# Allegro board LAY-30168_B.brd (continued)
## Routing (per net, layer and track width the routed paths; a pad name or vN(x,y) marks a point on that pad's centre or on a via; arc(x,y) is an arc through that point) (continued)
VAUD_3V3: length 28.1
  TOP w0.254: v2(131.06,26.8) 130.92,26.66 U13.32 ; U13.8 125.88,27.79 125.48,28.19 v2(125.22,28.19)
  TOP w0.305: U13.10 124.71,26.16 124.62,26.07 123.92,26.07 123.57,26.42 v2(123.57,26.67) 123.57,27.3 C105.1 C104.1 123.06,29.22 R93.2
  TOP w0.381: R94.1 v2(139.31,25.17)
  BOTTOM w0.305: C106.1 128.65,27.3 128.91,27.56 129.54,27.56 C107.1 v2(131.06,26.8) 131.83,27.56 135.13,27.56 136.91,25.78 138.7,25.78 v2(139.31,25.17) ; C106.1 123.88,27.3 123.57,27 v2(123.57,26.67) ; C106.1 v2(125.22,28.19)
VLDO_3V3: length 40.5
  TOP w0.381: R42.1 35.43,42.42 v2(35.43,41.91)
  BOTTOM w0.381: v2(35.43,41.91) 36.07,42.55 37.34,42.55 44.58,35.31 46.23,35.31 47.5,34.04 49.91,34.04 51.56,32.38 51.56,26.92 54.86,23.62 54.86,16.51 v2(56.13,15.24)
VSD_3V3: length 49.1
  TOP w0.254: C30.1 27.81,38.09 U37.A2
  TOP w0.381: v2(19.94,54.86) 19.15,54.08 J39.4 10.8,54.08 10.41,53.7 v2(10.41,53.21) v2(10.41,52.07) 10.41,43.58 C242.1 10.43,41.77 17.65,34.54 26.93,34.54 27.81,35.43 27.81,36.44 C30.1
  BOTTOM w0.381: C160.1 v2(10.41,53.21) ; v2(10.41,52.07) C161.1 ; v2(19.94,54.86) 20.57,55.49 R371.1
VTRG_FAULT_B: length 25.2
  TOP w0.254: 129.29,66.17 U31.A2
  TOP w0.305: 129.29,66.17 R215.2 128.52,66.57 128.21,66.88 127.3,66.88 126.87,67.31 v2(126.87,68.07) ; U38.A8 125.89,76.17 124.84,77.22 122.56,77.22 v2(122.3,77.47)
  BOTTOM w0.305: v2(122.3,77.47) 121.54,76.71 121.54,69.09 122.56,68.07 v2(126.87,68.07)
WALL_OV_BASE: length 1.7
  TOP w0.381: Q3.1 15.09,19.82 14.61,20.31 R5.2
WALL_OV_CTL: length 2.3
  TOP w0.381: R3.2 14.1,18.92 R5.1 D1.C
WALL_OVP_LED: length 3.9
  TOP w0.381: R10.1 16.26,17.79 16.39,17.91 Q3.3 16.39,19.81 16.37,19.82 D2.A
WDOG_B: length 198.3
  TOP w0.127: v2(29.21,46.23) 28.07,47.37 28.07,56.9 27.43,57.53 27.43,63.17 31.98,67.72 52.67,67.72 54.1,69.15 68.47,69.15 77.56,78.25 99.93,78.25 104.19,73.99 104.19,58.59 102.68,57.09 86.72,57.09 85.26,58.55 65.76,58.55 64.73,57.52 U1.D14 ; C60.1 39.12,18.87 v2(38.86,18.62)
  BOTTOM w0.127: v2(38.86,18.62) 41.27,21.03 41.27,36.25 37.07,40.45 32.19,40.45 30.48,42.16 30.48,43.69 29.21,44.96 v2(29.21,46.23)
N99781517: length 16.7
  TOP w0.305: R15.1 78.74,35.57 80.44,33.87 D4.C 81.28,33.87 J5.1 ; v2(86.36,36.83) R16.2 87.26,37.84 86.78,38.31 D5.C
  BOTTOM w0.381: J5.1 v2(86.36,36.83)
N99781633: length 5.4
  TOP w0.203: C22.1 59.06,46.81 58.85,47.02 58.85,49.99 58.8,50.04 58.8,50.96 U1.P8
  TOP w0.305: C22.1 C21.1
N99781636: length 1.1
  TOP w0.254: U1.M10 v1(60.37,52)
  BOTTOM w0.254: v1(60.37,52) 60.2,51.82 C25.1
N99781637: length 11.1
  TOP w0.254: 65.48,48.06 63.71,48.06 63.46,48.31 62.39,48.31 60.33,50.38 60.33,50.74 U1.P10
  TOP w0.305: 65.48,48.06 66.68,46.86 C24.1 C26.1
N99781682: length 10.2
  TOP w0.127: Y2.1 64.4,45.21 64.27,45.34 C42.1 64.27,47.49 64.07,47.69 63.56,47.69 63.3,47.94 62.24,47.94 59.94,50.24 59.94,50.55 59.72,50.77 59.72,51.34 U1.N9
N99781687: length 8.9
  TOP w0.127: Y2.2 63.37,45.21 63.49,45.34 C43.1 63.49,47.23 63.1,47.62 62.12,47.62 59.65,50.1 59.65,50.46 59.4,50.71 U1.P9
N99781694: length 12.4
  TOP w0.127: U1.N11 61.03,51.34 61.03,50.71 61.57,50.16 62.39,50.16 63.14,49.42 64.88,49.42 65.02,49.28 66.29,49.28 67.44,48.13 C40.1 R28.2 68.71,47.36 68.83,47.49 68.83,48.13 68.96,48.26 Y1.1
N99781701: length 16.9
  TOP w0.127: U1.P11 60.7,50.61 61.39,49.91 62.21,49.91 63.01,49.11 64.68,49.11 64.9,48.9 66.04,48.9 67.56,47.37 67.56,46.23 67.96,45.83 C39.1 R28.1 68.63,46.61 69.13,47.11 71.13,47.11 71.34,46.9 Y1.3 R30.1
N99781716: length 6.3
  TOP w0.381: R19.1 64.09,39.37 C29.1 R18.2 67,40.84 67.01,40.85 U2.3
N99781728: length 3
  TOP w0.254: R20.1 R19.2 U2.2
N99781740: length 2
  TOP w0.127: C60.2 R45.1 D9.C
N99781746: length 4.7
  TOP w0.254: U5.3 40.98,21.42 40.25,20.69 R41.1 40.63,19.56 D9.A D8.A
N99781747: length 1.9
  TOP w0.381: R36.1 38.1,13.97
N99781749: length 10.9
  TOP w0.254: U5.2 38.78,21.22 39.5,20.49 R41.2 39.12,19.56 C54.1 R38.1 35.18,19.56 34.67,19.05 v2(34.67,18.01)
  TOP w0.381: U3.8 v2(34.67,18.01)
  BOTTOM w0.381: v2(34.67,18.01) 33.94,17.27 R35.2
N99781753: length 2.4
  TOP w0.127: D8.C R43.2 C58.1
N99781762: length 0.9
  BOTTOM w0.381: v2(32,17.4) 32.13,17.27 R35.1
N99781782: length 3.5
  TOP w0.381: U3.7 36.79,17.36 37.09,17.66 R39.1 R36.2
N99808656: length 15
  TOP w0.254: U1.J6 v1(57.12,54.59)
  INT1 w0.102: 56.8,52.97 56.34,52.97 56.15,52.78 56.15,52.3 56.17,52.32 57.27,52.32 57.44,52.49 57.44,52.96 57.12,53.29 56.8,52.97
  INT1 w0.305: v2(51.05,48.84) 51.64,48.84 52.58,49.78 53.14,49.78 55.42,52.07 55.92,52.07 56.15,52.3
  INT1 w0.33: 57.12,53.29 v1(57.12,54.59)
  BOTTOM w0.127: C77.1 v1(57.12,54.59)
  BOTTOM w0.305: v2(51.05,48.84) 51.44,49.23 51.44,49.78 R61.2
N99815013: length 4.1
  TOP w0.254: U16.3 v2(107.95,42.07)
  BOTTOM w0.381: L13.2 C140.1 C141.1 108.2,41.82 v2(107.95,42.07)
N99815680: length 2.9
  TOP w0.254: U16.2 107.45,42.33 v2(107.19,42.07)
  BOTTOM w0.381: C143.1 v2(107.19,42.07) 106.81,42.45 C142.1
N99815919: length 4.6
  TOP w0.254: C149.1 109.73,30.12 J19.6
N99815924: length 4.6
  TOP w0.254: J19.5 C150.1
N99816488:
  vias: v2(99.69,9.05) v2(100.97,9.05) v2(117.47,9.05) v2(118.75,9.05)
N99820323: length 3.4
  TOP w0.127: U16.10 111.74,44.25 112.17,43.81 112.78,43.81 113.07,43.52 113.07,43.05 R133.1
N99827287: length 1.9
  TOP w0.127: U13.27 C113.1
N99827729: length 3.4
  TOP w0.127: U13.15 124.62,23.65 122.93,21.96 R96.2
N99827749: length 2.5
  TOP w0.127: R98.2 123.71,24.14 124.22,24.65 U13.13
N99827769: length 2.4
  TOP w0.127: R99.2 123.3,25.41 123.56,25.15 U13.12
N99827789: length 4.1
  TOP w0.127: R100.2 123.44,20.83 123.44,21.84 124.75,23.15 U13.16
N99827809: length 2.8
  TOP w0.127: R101.2 123.34,22.88 124.61,24.15 U13.14
N99827829: length 3
  TOP w0.127: R102.2 122.93,26.29 123.56,25.66 U13.11
N99827958: length 5
  TOP w0.381: R118.2 C134.2 145.55,20.72 C232.1 145.54,20.07 146.69,18.92 J16.1
N99827962: length 4.8
  TOP w0.381: R120.2 C136.1 144.04,20.7 C232.2 144.79,19.69 144.15,19.05 J16.2
N99828318: length 5
  TOP w0.381: J17.1 139.7,18.92 138.68,19.95 C233.1 139.44,20.7 C135.2 139.46,20.72 R119.2
N99828322: length 4.9
  TOP w0.381: R121.2 136.16,20.71 C137.1 137.92,20.71 C233.2 137.93,19.95 137.16,19.18 J17.2
N99833003:
  vias: v2(88.9,2.54) v2(94.03,2.54)
N99833020: length 10.5
  TOP w0.127: R71.1 v2(93.34,7.09) 93.34,6.23 92.09,4.97 J9.4 ; U9.3 90.18,9.49 v2(89.79,9.88)
  BOTTOM w0.127: v2(89.79,9.88) 90.55,9.12 91.69,9.12 92.08,8.74 92.08,7.75 92.74,7.09 v2(93.34,7.09)
N99833038: length 15.2
  TOP w0.119: R68.1 L5.1 v2(91.33,10.01) 91.18,9.86 U9.1 ; J9.2 90.79,4.82 91.02,5.05 91.02,5.38 91.76,6.11 91.76,6.28 91.64,6.4 v2(91.51,6.4)
  BOTTOM w0.119: v2(91.33,10.01) 91.15,10.18 91.15,10.79 90.58,11.35 89.49,11.35 89.03,10.9 89.03,7.88 89.78,7.13 91.4,7.13 91.68,6.84 91.68,6.57 v2(91.51,6.4)
N99833040: length 15.3
  TOP w0.119: R69.1 L5.4 v2(90.53,10.01) 90.68,9.86 U9.2 ; v2(92.35,6.4) 92.2,6.4 92,6.21 92,6.01 91.27,5.28 91.27,5.06 91.44,4.88 J9.3
  BOTTOM w0.119: v2(90.53,10.01) 90.7,10.01 90.91,10.22 90.91,10.68 90.48,11.11 89.59,11.11 89.27,10.79 89.27,7.98 89.88,7.37 90.5,7.37 90.62,7.49 90.62,7.6 90.74,7.71 90.98,7.71 91.1,7.6 91.1,7.49 91.22,7.37 91.5,7.37 91.92,6.95 91.92,6.61 92.13,6.4 v2(92.35,6.4)
N99834989:
  vias: v2(78.23,2.54) v2(83.36,2.54)
N99835007: length 12.2
  TOP w0.119: U11.1 80.51,9.86 v2(80.66,10.01) L8.1 R83.1 ; v2(81.37,8.16) 81.67,7.86 81.67,7.09 80.32,5.75 80.32,5.15 80.12,4.95 J10.2
  BOTTOM w0.119: v2(80.66,10.01) 80.43,10.01 80.31,10.13 80.31,10.45 80.43,10.57 81.26,10.57 81.82,10.01 81.82,9.36 81.7,9.24 81.6,9.24 81.48,9.12 81.48,8.89 81.6,8.77 81.7,8.77 81.82,8.65 81.82,8.42 81.56,8.16 v2(81.37,8.16)
N99835017: length 12.2
  TOP w0.119: J10.3 80.77,4.95 80.57,5.15 80.57,5.65 81.92,6.99 81.92,7.86 v2(82.21,8.16) ; R84.1 L8.4 v2(79.86,10.01) 80.01,9.86 U11.2
  BOTTOM w0.119: v2(82.21,8.16) 82.06,8.31 82.06,10.11 81.36,10.82 80.33,10.82 80.07,10.55 80.07,10.22 v2(79.86,10.01)
N99838171: length 1
  TOP w0.127: R175.1 D12.C
N99842431: length 4.6
  TOP w0.254: R115.2 123.45,55.83 123.63,56.01 124.61,56.01 124.84,56.24 124.84,56.6 124.66,56.78 U14.1
  TOP w0.381: R114.1 122.68,55.12 122.95,55.38 R115.2
N99842486: length 1.5
  TOP w0.381: C139.1 R122.2
N99842500: length 1.7
  TOP w0.508: T1.1 C131.2
N99842510: length 3.8
  TOP w0.508: R116.1 C132.1 T1.6
N99842524: length 1
  TOP w0.381: R115.1 C132.2
N99842534: length 10.4
  TOP w0.254: v2(124.97,58.04) 124.73,57.8 U14.3 ; v2(120.52,55.38) 120.79,55.12 R114.2 121.29,55.37 122.04,56.12 R117.1 122.5,56.34 122.95,56.78 U14.6
  BOTTOM w0.305: v2(124.97,58.04) 123.18,58.04 v2(120.52,55.38)
N99842546: length 5.5
  TOP w0.254: U14.4 122.92,57.8 122.56,58.17
  TOP w0.381: J15.2 120.02,60.71 122.56,58.17
N99842626: length 6.2
  TOP w0.127: J38.1 121.01,47.88 R124.1 121.68,49.42 122.3,50.04 122.3,51.32 122.17,51.44 U15.2
N99842704: length 12.4
  TOP w0.508: J18.1 143.67,47.89 143.16,48.4 T2.3
N99903207: length 1.9
  TOP w0.381: L10.1 R97.2 C230.2
N99903209: length 2.1
  TOP w0.381: L11.1 R103.1 133.73,25.78 C231.2
N99903219: length 30.9
  TOP w0.381: v2(136.14,23.75) C115.1 L11.2 ; TVS4.2 138.55,37.6 v2(138.68,37.47)
  TOP w0.508: J12.3 TVS4.2
  BOTTOM w0.381: v2(136.14,23.75) 137.41,23.75 138.18,24.51 140.59,24.51 141.99,25.91 143.89,25.91 144.4,26.42 144.4,27.56 144.02,27.94 139.95,27.94 137.9,30 137.9,36.68 v2(138.68,37.47)
N99903223: length 8.6
  TOP w0.381: L10.2 C114.2 136.02,28.96 136.4,28.57 136.4,26.42 136.82,26 TVS2.2
  TOP w0.508: TVS2.2 137.9,26.1 J12.2
N99903738: length 15.1
  TOP w0.381: L12.2 v2(132.59,33.27)
  BOTTOM w0.305: v2(132.59,33.27) 132.59,31.65 137.31,26.92 v2(143.51,26.92)
N99904959: length 2.4
  TOP w0.305: R110.1 R107.2 C123.2
N99904961: length 4.3
  TOP w0.305: L12.1 C129.1 C128.1 129.67,31.88 C125.2
N99904975: length 2.7
  TOP w0.305: R107.1 R104.2 C119.1 C120.1
N99907436: length 1.8
  TOP w0.305: R113.2 R112.2 123.87,33.54 C124.2
N99907447: length 6.8
  TOP w0.305: R111.2 123.69,34.79 123.56,34.66 R109.2 R112.1 v2(125.22,34.29)
  TOP w0.381: C126.1 v2(126.11,31.24)
  BOTTOM w0.305: v2(125.22,34.29) 125.22,32.13 v2(126.11,31.24)
N99907449: length 8.8
  TOP w0.305: R108.2 122.69,34.79 122.82,34.66 R109.1 R106.2 v2(121.16,34.29)
  TOP w0.381: C122.1 v2(124.33,31.24)
  BOTTOM w0.305: v2(121.16,34.29) 121.16,32.64 122.56,31.24 v2(124.33,31.24)
N99907458: length 3.6
  TOP w0.305: C124.1 122.51,33.54 R106.1 R105.2 C116.1 C117.1
N99907542: length 3.3
  TOP w0.305: P1.1 122.24,37.27 122.69,36.82 R108.1
N99907546: length 3.3
  TOP w0.305: R111.1 123.69,36.82 124.14,37.27 P1.2
N99909350: length 5.8
  TOP w0.254: R269.1 R268.2 U32.7
N99909356: length 2.8
  TOP w0.254: U32.16 R266.1
N99909379: length 4.9
  TOP w0.254: U32.6 60.46,73.29 59.69,72.52 R273.1
N99909383: length 3.9
  TOP w0.254: R272.1 U32.4
N99909400: length 3.8
  TOP w0.254: C190.1 57.02,78.23 57.28,77.97 U32.2
N99909418: length 5.3
  TOP w0.254: C189.1 61.46,73.79 U32.8
N99909466: length 4.9
  TOP w0.254: R264.1 66.04,75.56 65.13,76.47 U32.9
N99909468: length 5
  TOP w0.254: U32.11 65.28,77.47 66.42,78.61 R263.1
N99909488: length 5.8
  TOP w0.254: R265.2 R267.1 66.04,76.58 65.65,76.97 U32.10
N99912703: length 3.3
  TOP w0.305: U8.5 v2(94.36,66.68) C88.1 R63.1
  vias: v2(100.71,68.71) v2(101.35,68.71)
N99917011: length 12.6
  BOTTOM w0.254: J26.2 22.86,37.99 J25.3
N99917059: length 142.9
  TOP w0.127: J24.9 4.33,79.41 4.33,32.25 8.89,27.69 25.78,27.69 28.32,25.15 28.32,14.69 30.1,12.91 30.1,3.3 31.74,1.66 71.63,1.66 R276.1
N99917061: length 144.6
  TOP w0.127: J24.10 3.7,79.88 3.7,31.99 8.51,27.18 25.57,27.18 27.81,24.94 27.81,14.48 29.59,12.7 29.59,3.3 31.53,1.36 72.35,1.36 R277.1
N99917215: length 3.3
  TOP w0.381: D14.C J25.5
N100002783: length 3.4
  TOP w0.254: U1.K3 v1(55.17,53.3)
  BOTTOM w0.102: v1(55.17,53.3) 54.85,52.97 54.85,52.25 C41.1 54.18,52.02 53.87,51.71 R32.2
N100054133: length 4
  TOP w0.381: Q4.1 17.48,14.15 17.01,14.61 R11.1 R10.2
N100054253: length 14.5
  TOP w0.381: D2.C R4.2 16.37,23.86 16.5,24 C5.2 R8.1 v2(17.4,23.5) ; Q2.3 v2(9.88,18.41)
  BOTTOM w0.381: v2(17.4,23.5) 12.32,18.41 v2(9.88,18.41)
N100054255: length 1
  TOP w0.381: R8.2 R9.1
N100054257: length 20.9
  TOP w0.381: R9.2 v2(20.45,23.5)
  BOTTOM w0.381: v2(20.45,23.5) 18.54,21.59 18.54,10.65 SW1.5
N100054299: length 7
  TOP w0.254: R4.1 15.62,22.63 15.62,20.29 15.72,20.19 15.72,18.65 15.37,18.3 Q3.2 14.97,18.3
  TOP w0.381: R4.1 15.62,24.13 15.49,24.26 C5.1
N100054525: length 2
  TOP w0.381: D3.3 R7.2
N100054552: length 1.9
  TOP w0.381: D3.1 v2(17.4,20.02)
  BOTTOM w0.381: R6.2 v2(17.4,20.02)
N100054568: length 2.2
  TOP w0.381: Q4.3 D3.2
N100192090: length 4.5
  TOP w0.127: v2(135.76,6.1) 135.96,6.3 J35.19
  BOTTOM w0.127: R230.2 136.02,6.36 v2(135.76,6.1)
N100192374: length 4
  TOP w0.127: L17.1 139.57,10.04 139.57,9.86 137.96,8.25 J35.23
N100226351: length 1.9
  TOP w0.127: SW7.5 R246.2
N100226419: length 1.9
  TOP w0.127: SW7.6 R245.2
N100226426: length 1.9
  TOP w0.127: SW7.7 R244.2
N100226433: length 1.9
  TOP w0.127: SW7.8 R243.2
N100226440: length 1.9
  TOP w0.127: SW6.5 R242.2
N100226447: length 1.9
  TOP w0.127: SW6.6 R241.2
N100226454: length 1.9
  TOP w0.127: SW6.7 R240.2
N100226461: length 1.9
  TOP w0.127: SW6.8 R239.2
N100226670: length 1.9
  TOP w0.127: SW5.5 R238.2
N100226677: length 1.9
  TOP w0.127: SW5.6 R237.2
N100226684: length 1.9
  TOP w0.127: SW5.7 R236.2
N100226691: length 1.9
  TOP w0.127: SW5.8 R235.2
N100290781: length 3.7
  BOTTOM w0.127: R67.2 J8.A31
N100350746: length 3.1
  TOP w0.305: R27.2 D7.A D6.A R29.1
N100395820: length 4.5
  TOP w0.508: C131.1 135.89,57.4 136.4,57.91 139.16,57.91 J14.2
N100395835: length 11.6
  TOP w0.508: J14.1 143.67,59.66 142.86,60.46 T1.3
N100538650: length 6.5
  TOP w0.381: Q9.3 44.45,36.45 44.83,36.83 44.83,38.48 44.38,38.94 R47.2
N100585505: length 3.9
  TOP w0.127: J39.9 24.11,56.28 v2(24.13,56.26)
  BOTTOM w0.127: R313.2 R173.1 v2(24.13,56.26) R320.1
N100756566: length 19.3
  TOP w0.254: TP22.1 v2(73.79,44.96) ; U1.N10 v1(60.37,51.35)
  BOTTOM w0.254: v1(60.37,51.35) 60.92,51.35 62.76,49.5 72.29,49.5 73.23,48.56 73.23,45.52 v2(73.79,44.96)
N100757315: length 5.7
  TOP w0.102: U1.N12 61.68,51.34 61.68,50.9 61.89,50.69 62.62,50.69 62.99,50.32 63.47,50.32
  TOP w0.254: 63.47,50.32 64.03,50.32 64.34,50.62 TP23.1
N100763661: length 26.4
  TOP w0.127: J24.5 15.68,65.53 15.55,65.41 14.73,65.41 14.61,65.28 14.61,65.03 14.73,64.9 15.68,64.9 15.81,64.77 15.81,64.52 15.68,64.39 14.73,64.39 14.61,64.26 14.61,64.01 14.73,63.88 15.68,63.88 15.81,63.76 15.81,63.5 15.68,63.38 14.99,63.38 14.86,63.25 14.86,62.99 14.99,62.87 15.55,62.87 15.68,62.74 15.68,61.4 v2(15.24,60.96)
  BOTTOM w0.127: R278.1 15.11,60.83 v2(15.24,60.96)
N100763684: length 27.6
  TOP w0.127: v2(17.27,58.93) 17.27,61.47 18.03,62.23 18.03,62.7 17.91,62.82 17.35,62.82 17.22,62.95 17.22,63.2 17.35,63.33 18.09,63.33 18.22,63.46 18.22,63.71 18.09,63.84 17.4,63.84 17.27,63.97 17.27,64.22 17.4,64.35 18.09,64.35 18.22,64.47 18.22,64.73 18.09,64.85 17.4,64.85 17.27,64.98 17.27,65.24 17.4,65.36 18.09,65.36 18.22,65.49 J24.4
  BOTTOM w0.127: R279.1 17.27,58.92 v2(17.27,58.93)
N100763722: length 26.8
  TOP w0.127: J24.6 13.14,61.21 v2(13.39,60.96)
  BOTTOM w0.127: v2(13.39,60.96) 13.39,58.49 15.11,56.77 R280.1
N100763741: length 28.6
  TOP w0.127: v2(17.78,57.27) 17.91,57.4 17.91,60.07 20.19,62.36 20.19,63.48 20.07,63.6 19.79,63.6 19.66,63.73 19.66,63.98 19.79,64.11 20.63,64.11 20.76,64.24 20.76,64.49 20.63,64.62 19.79,64.62 19.66,64.75 19.66,65 19.79,65.13 20.63,65.13 20.76,65.25 J24.3
  BOTTOM w0.127: R281.1 v2(17.78,57.27)
N100763780: length 19.5
  TOP w0.127: U20.F2 32.47,60.57 32.47,62.06 33.02,62.61 33.38,62.61 33.51,62.48 33.51,61.98 33.64,61.85 33.89,61.85 34.02,61.98 34.02,62.48 34.15,62.61 34.4,62.61 34.53,62.48 34.53,61.98 34.65,61.85 34.91,61.85 35.04,61.98 35.04,62.48 35.16,62.61 35.42,62.61 35.54,62.48 35.54,61.98 35.67,61.85 35.92,61.85 36.05,61.98 36.05,62.48 36.18,62.61 36.43,62.61 36.56,62.48 36.56,61.98 36.69,61.85 36.94,61.85 37.07,61.98 37.07,62.48 37.19,62.61 37.45,62.61 37.58,62.48 37.58,61.98 37.7,61.85 37.96,61.85 38.08,61.98 38.08,62.48 38.21,62.61 38.46,62.61 38.59,62.48 38.59,62.1 38.72,61.98 38.97,61.98 39.1,62.1 39.1,62.48 39.23,62.61 39.56,62.61 39.69,62.48 39.69,62.1 39.81,61.98 40.07,61.98 40.19,62.1 40.19,62.74 40.32,62.87 40.77,62.87 40.9,62.74 R283.2
N100784802: length 62.9
  TOP w0.127: v2(66.55,30.73) 65.98,30.16 52.01,30.16 51.18,29.34 37.98,29.34 J23.1
  BOTTOM w0.127: v2(66.55,30.73) 73.41,30.73 79.76,37.08 79.76,48.13 80.78,49.16 R285.1
N100784828: length 59.4
  TOP w0.127: J23.2 40.01,29.84 50.8,29.84 51.69,30.73 v2(65.41,30.73)
  BOTTOM w0.127: R286.1 79.88,49.15 79.38,48.64 79.38,37.34 73.28,31.24 65.91,31.24 v2(65.41,30.73)
N100784849: length 115.6
  TOP w0.127: R287.1 91.31,52.96 92.08,52.96 92.76,52.27 102.92,52.27 108.09,57.45 108.09,78.35 103.76,82.68 95.63,82.68 92.08,86.23 56.39,86.23 49.4,79.25 41.41,79.25 J22.4
N100784872: length 111.3
  TOP w0.127: v2(86.56,50.8) 103.28,50.8 110.26,57.78 v2(112.39,57.78)
  BOTTOM w0.127: v2(86.56,50.8) 86.99,50.37 R288.1 ; v2(112.39,57.78) 112.39,61.59 87.07,86.92 62.79,86.92 56.47,80.6 J22.1
N100784902: length 112.2
  BOTTOM w0.127: J22.2 46.33,81.79 54.36,81.79 59.8,87.23 87.34,87.23 113.03,61.54 113.03,54.86 118.24,49.66 118.24,34.49 117.35,33.6 R289.1
N100784935: length 66.1
  TOP w0.127: v2(65.41,31.75) 51.69,31.75 50.29,30.35 42.05,30.35 J23.3 ; v2(87.63,48.01) 86.11,48.01 84.72,49.39 83.63,49.39 83.28,49.73 78.41,49.73 v2(78.23,49.91)
  BOTTOM w0.127: R290.1 v2(87.63,48.01) ; v2(65.41,31.75) 66.67,33.02 71.88,33.02 75.82,36.96 75.82,49.91 76.33,50.42 77.72,50.42 v2(78.23,49.91)
N100784954: length 64.9
  TOP w0.127: v2(88.77,45.85) 87,47.62 86.03,47.62 84.57,49.09 83.48,49.09 83.14,49.43 77.19,49.43 v2(76.71,49.91) ; J23.4 44.08,30.86 49.91,30.86 51.31,32.26 66.04,32.26 v2(66.55,31.75)
  BOTTOM w0.127: v2(66.55,31.75) 67.3,32.5 72.12,32.5 76.26,36.64 76.26,49.47 v2(76.71,49.91) ; R291.1 v2(88.77,45.85)
N100873109: length 1.1
  TOP w0.381: R18.1 68.07,38.62 R293.2
N100881534: length 20.4
  TOP w0.127: v2(56.13,27.56) 55.75,27.18 U33.6
  BOTTOM w0.127: v2(56.13,27.56) 56.13,28.87 56.01,28.99 55.63,28.99 55.5,29.12 55.5,29.38 55.63,29.5 56.01,29.5 56.13,29.63 56.13,29.88 56.01,30.01 55.5,30.01 55.37,30.14 55.37,30.39 55.5,30.52 56.01,30.52 56.13,30.65 56.13,30.9 56.01,31.03 55.5,31.03 55.37,31.15 55.37,31.41 55.5,31.53 56.01,31.53 56.13,31.66 56.13,32 52.32,35.81 52.32,39.52 52.63,39.83 52.63,40.65 R154.2
N100881537: length 21.3
  TOP w0.127: v2(59.18,24.89) 59.44,24.64 U33.1
  BOTTOM w0.127: R153.2 50.29,38.49 50.3,38.48 50.3,35.93 53.09,33.15 53.09,29.84 58.05,24.89 R360.2 58.3,24.89 v2(59.18,24.89)
N100881743: length 19.7
  TOP w0.127: U33.5 v2(57.91,28.45)
  BOTTOM w0.127: R155.1 55.18,35.88 55.18,35.7 54.72,35.24 54.72,35.06 54.9,34.88 55.08,34.88 55.54,35.34 55.72,35.34 55.87,35.2 55.87,35.02 55.4,34.55 55.4,34.37 55.58,34.19 55.76,34.19 56.16,34.59 56.34,34.59 56.55,34.38 56.55,34.2 56.09,33.75 56.09,33.57 56.27,33.39 56.45,33.39 56.78,33.72 56.96,33.72 57.15,33.53 57.78,33.53 57.91,33.4 57.91,33.06 57.78,32.94 57.4,32.94 57.28,32.81 57.28,32.56 57.4,32.43 57.78,32.43 57.91,32.3 57.91,32.05 57.78,31.92 57.4,31.92 57.28,31.79 57.28,31.46 57.4,31.33 57.78,31.33 57.91,31.2 57.91,30.95 57.78,30.82 57.4,30.82 57.28,30.7 57.28,29.08 v2(57.91,28.45)
N100881750: length 20.4
  TOP w0.127: v2(59.18,25.91) U33.2
  BOTTOM w0.127: v2(59.18,25.91) 58.93,25.91 58.4,26.43 58.22,26.43 57.83,26.04 57.65,26.04 57.47,26.22 57.47,26.4 58.24,27.17 58.24,27.35 58.07,27.53 57.89,27.53 57.11,26.76 56.93,26.76 56.75,26.94 56.75,27.12 57.15,27.51 57.15,27.69 56.64,28.19 56.64,32.35 53.59,35.4 53.59,35.72 53.72,35.85 53.98,35.85 54.1,35.98 54.1,36.23 53.98,36.36 53.72,36.36 53.59,36.49 R156.1
N100881757: length 20.4
  TOP w0.127: v2(60.07,27.18) U33.3
  BOTTOM w0.127: R157.1 58.16,38.49 59.69,36.96 59.69,36.4 59.82,36.27 60.07,36.27 60.2,36.15 60.2,35.89 60.07,35.76 59.44,35.76 59.31,35.64 59.31,35.4 59.44,35.27 60.07,35.27 60.2,35.15 60.2,34.89 60.07,34.77 59.82,34.77 59.69,34.64 59.69,34.39 59.82,34.26 60.07,34.26 60.2,34.13 60.2,33.88 60.07,33.75 59.82,33.75 59.69,33.62 59.69,33.37 59.82,33.24 60.07,33.24 60.2,33.12 60.2,32.86 60.07,32.73 59.82,32.73 59.69,32.61 59.69,32.35 59.82,32.23 60.07,32.23 60.2,32.1 60.2,31.85 60.07,31.72 59.69,31.72 59.56,31.59 59.56,31.27 59.69,31.14 60.05,31.14 60.17,31.01 60.17,30.76 60.05,30.63 59.82,30.63 59.69,30.51 59.69,29.84 60.71,28.83 R359.2 v2(60.07,27.18)
N100881764: length 20.8
  TOP w0.127: v2(59.18,28.45) 56.64,25.91 U33.7
  BOTTOM w0.127: R358.2 v2(59.18,28.45) 58.35,29.28 58.35,29.75 58.23,29.88 58.04,29.88 57.91,30 57.91,30.26 58.04,30.39 58.61,30.39 58.73,30.51 58.73,30.77 58.61,30.89 58.48,30.89 58.35,31.02 58.35,31.99 58.48,32.12 58.93,32.12 59.05,32.24 59.05,32.5 58.93,32.62 58.48,32.62 58.35,32.75 58.35,33 58.48,33.13 58.93,33.13 59.05,33.26 59.05,33.51 58.93,33.64 58.48,33.64 58.35,33.77 58.35,34.04 58.48,34.17 59.05,34.17 59.18,34.3 59.18,34.54 59.05,34.67 58.55,34.67 58.42,34.8 58.42,36.46 R158.1
N100937722: length 2.1
  TOP w0.127: U19.A4 55.74,42.31 v1(55.63,42.42)
  BOTTOM w0.127: R169.2 55.89,42.16 v1(55.63,42.42) 55.63,42.53 55.58,42.58 R168.2
N100939369: length 2.7
  BOTTOM w0.127: R425.1 R424.1 R171.2 R427.2
N100979684: length 2.5
  TOP w0.381: R305.2 57.16,10.41 R304.1 55.98,9.53 U4.4
N101050998: length 4.4
  TOP w0.127: U16.32 105.98,43.75 104.78,42.55 C234.1 103.64,42.55 R322.1 R323.2
N101100421: length 2
  BOTTOM w0.127: R313.1 R372.2 R371.2
N101108824: length 1.5
  TOP w0.127: D18.A 100.83,40.13 R316.2
N101140611: length 6.5
  TOP w0.127: Q15.3 81.92,15.62 82.29,15.25 R329.2 R333.1 R332.2 85.83,15.14 U34.A1
N101140956: length 3.6
  TOP w0.127: U34.A2 86.23,14.74 R349.2 R334.2
N101141371: length 3.1
  TOP w0.127: R335.1 86.63,12.97 U34.A3
N101141921: length 4
  TOP w0.102: U35.A2 89.03,23.62
  TOP w0.127: R341.2 R350.2 89.03,25.15 89.03,23.62
N101141946: length 3.5
  TOP w0.102: U35.A3 89.43,23.39 89.66,23.62
  TOP w0.127: 89.66,23.62 R342.1
N101142201: length 5
  TOP w0.102: U35.A1 88.63,23.62
  TOP w0.127: R344.2 R346.2 R348.1 88.63,25.3 88.63,23.62
N101241745: length 4.7
  TOP w0.381: U12.3 v2(74.05,21.21)
  BOTTOM w0.381: v2(74.05,21.21) 73.91,21.35 C99.1 C98.1 74.8,20.58 R85.2
N101242370: length 7.6
  TOP w0.127: R88.2 v2(63.92,12.11) ; R89.1 v2(68.94,12.11)
  BOTTOM w0.127: v2(63.92,12.11) 64.18,11.85 C102.1 68.69,11.85 v2(68.94,12.11)
N101242461: length 14.8
  TOP w0.107: R87.1 FL1.4 66.2,17.26 66.3,17.37 66.3,18.28 67.07,19.05 74.43,19.05 74.82,18.66 74.82,18.4 74.92,18.29 75.22,18.29 75.32,18.19 U12.7
N101242463: length 14.4
  TOP w0.107: U12.6 74.05,18.19 74.16,18.29 74.45,18.29 74.56,18.4 74.56,18.55 74.32,18.79 73.83,18.79 73.73,18.68 73.73,18.52 73.62,18.41 73.41,18.41 73.3,18.52 73.3,18.68 73.19,18.79 67.18,18.79 66.56,18.18 66.56,17.37 66.67,17.26 FL1.3 R91.1
N101242940: length 3.8
  TOP w0.127: U12.8 v2(76.59,16) 76.59,15.25 R326.1
  BOTTOM w0.127: R90.2 R92.2 v2(76.59,16)
N101351285: length 4
  TOP w0.127: U19.C2 53.24,40.26 52.7,40.26 52.07,40.89 v1(51.92,40.89)
  BOTTOM w0.127: v1(51.92,40.89) R356.2 51.05,40.26 R294.2
N101351783: length 3.7
  TOP w0.127: J35.21 136.96,6.55 v2(137.54,5.97)
  BOTTOM w0.127: v2(137.54,5.97) 137.67,6.1 C248.1 137.67,7.74 L19.1
N101474013: length 1.2
  TOP w0.127: U19.B2 53.39,40.76 v1(53.21,40.94)
  BOTTOM w0.127: R361.2 53.28,41.01 v1(53.21,40.94)
N101474117: length 1.3
  TOP w0.127: U19.D3 54.74,38.48 v1(54.99,38.23)
  BOTTOM w0.127: v1(54.99,38.23) R362.2
N101474142: length 1.2
  TOP w0.102: U19.D2 53.95,38.76 v1(54.23,38.48)
  BOTTOM w0.102: R363.2 53.6,38.48 v1(54.23,38.48)
N101474197: length 1.7
  TOP w0.127: v1(56.39,40.26) 55.89,39.76 U19.C4
  BOTTOM w0.127: R364.2 56.65,40 v1(56.39,40.26)
N101474201: length 1.5
  TOP w0.127: U19.D4 56.02,38.48 v1(56.26,38.48)
  BOTTOM w0.127: v1(56.26,38.48) 56.39,38.48 R365.2
N101481296: length 1.5
  TOP w0.127: U19.C3 54.6,39.76 v1(54.1,40.26)
  BOTTOM w0.127: R366.2 54.23,40.39 v1(54.1,40.26)
N101508071: length 3.1
  TOP w0.254: U37.B1 28.52,40.01 28.45,40.07 R29.2
N101529304: length 3.4
  TOP w0.305: U38.E4 v2(130.01,72.57) ; U38.E5 v2(130.01,73.37) ; U38.F4 v2(130.81,72.57)
  BOTTOM w0.305: C254.1 130.18,73.53 v2(130.01,73.37) ; 130.94,71.75 130.81,71.88 v2(130.81,72.57)
  vias: v2(125.48,65.41) v2(126.36,66.05) v2(126.36,65.41)
N101531474: length 2.7
  TOP w0.127: U40.4 145.09,83.38 144.91,83.56 R377.1 R378.2
N101535047: length 9.1
  TOP w0.127: U38.E3 130.81,71.77 130.81,70.23 131.83,69.22 136.65,69.22 R379.2
N101535139: length 7.9
  TOP w0.127: R380.2 136.65,70.87 135.76,69.98 132.84,69.98 132.42,70.4 132.42,71.53 132.17,71.77 131.6,71.77 U38.F3
N101537312: length 3.5
  TOP w0.127: U38.A6 124.44,74.57 R381.2
N101537315: length 4.7
  TOP w0.127: R382.2 125.06,74.96 127.37,74.96 127.77,74.57 U38.B6
N101537383: length 3.8
  TOP w0.127: U38.A4 125.42,72.97 124.46,72.01 R383.2
N101544777: length 5.5
  TOP w0.127: R387.2 125.6,78.49 126.73,77.36 128.25,77.36 128.64,76.97 U38.C9
N101546218: length 1.5
  TOP w0.127: D20.A 139.69,72.9 R392.2
N101549401: length 13.3
  TOP w0.127: J43.1 140.84,92.33 145.29,92.33 145.68,91.94 R400.2 R394.2 143.78,89.92 143.66,89.79 U44.2
N101549759: length 1.6
  TOP w0.127: U44.5 141.22,88.9 R402.1
N101553401: length 3.3
  TOP w0.127: U45.6 116.64,94.05 115.82,94.87 R413.2
N101556572: length 1.8
  TOP w0.127: U48.7 95.76,96.13 R416.1
N101556596: length 1.7
  TOP w0.127: U48.6 96.26,96.26 R417.1
N101557543: length 1.9
  TOP w0.127: U48.5 96.76,94.25 97.03,93.97 R418.1
N101571275: length 16.3
  TOP w0.127: U38.C1 128.04,69.8 122.68,69.8 121.92,70.56 121.62,70.56 C273.1 121.03,70.48 117.86,70.48 117.6,70.23 Y4.2
N101571285: length 15.8
  TOP w0.127: U38.B1 127.55,70.1 122.81,70.1 122.05,70.87 121.67,70.87 C274.1 120.9,70.87 117.98,70.87 117.6,71.25 Y4.1
N101599117: length 2.5
  TOP w0.127: U31.A3 130.48,66.8 129.41,66.8 R351.1
N101599129: length 5.7
  TOP w0.254: U31.A1 130.03,65.77
  TOP w0.305: 130.03,65.77 129.79,65.53 128.14,65.53 R214.1 127.25,64.64 R216.2 R212.2
N101616215: length 3.2
  TOP w0.127: v2(53.85,43.94) 54.74,43.05 U19.A3
  BOTTOM w0.127: R424.2 53.33,43.94 v2(53.85,43.94)
N101616337: length 2.2
  TOP w0.127: v2(53.85,43.23) 53.85,42.55 53.74,42.43 U19.A2
  BOTTOM w0.127: v2(53.85,43.23) 53.8,43.18 R425.2
N101616340: length 1.6
  TOP w0.127: v1(56.26,42.42) 56.26,42.24 U19.A5
  BOTTOM w0.127: R426.2 56.46,42.62 v1(56.26,42.42)
N101658009: length 1.5
  BOTTOM w0.127: R170.2 56.25,44.02 R426.1

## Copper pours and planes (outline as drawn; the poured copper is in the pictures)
5V_SDA_PSW on TOP (solid shape): 133.83,67.19 133.83,65.63 133.6,65.41 131.95,65.41 131.81,65.55 131.81,65.97 131.73,66.04 131.47,66.04 131.41,66.1 131.41,66.24 131.46,66.29 132.12,66.29 132.29,66.46 132.29,66.56 133.02,67.29 133.72,67.29
5V_SYS on TOP (solid shape): 87.5,20.57 87.5,18.8 87.38,18.67 86.36,18.67 85.72,19.3 85.72,20.57 85.83,20.67 87.4,20.67
5V_SYS on TOP (solid shape): 30.35,22.23 30.35,21.95 30.35,21.74 30.33,21.72 30.33,21.19 30.23,21.08 28.7,21.08 28.57,21.21 28.57,22.4 28.65,22.48 30.1,22.48
5V_SYS on TOP (solid shape): 36.58,40.51 36.58,38.73 36.45,38.61 35.18,38.61 34.8,38.99 33.02,38.99 32.64,39.37 32.64,41.15 32.89,41.4 35.69,41.4
5V_SYS on TOP (solid shape): 92.56,63.65 92.56,63.25 92.58,63.23 92.58,60.09 92.58,59.94 94.11,58.42 94.11,57.91 94.08,57.89 91.03,57.89 91.01,57.91 91.01,63.58 91.31,63.88 92.33,63.88
5V_SYS on TOP (solid shape): 82.91,11.58 82.91,10.69 83.19,10.41 83.95,10.41 84.07,10.29 84.07,8.89 83.95,8.76 82.8,8.76 81.53,10.03 81.53,11.56 81.66,11.68 82.8,11.68
5V_SYS on TOP (solid shape): 54.74,14.99 54.74,9.14 54.61,9.02 52.45,9.02 52.32,9.14 52.32,10.03 52.45,10.16 53.85,10.16 53.98,10.29 53.98,11.18 53.72,11.43 52.35,11.43 52.2,11.58 52.2,12.97 52.2,12.98 52.2,13.18 52.2,13.19 52.2,14.99 52.32,15.11 54.61,15.11
5V_SYS on TOP (solid shape): 99.06,27.56 99.06,19.3 99.31,19.05 124.57,19.05 125.48,18.15 128.79,18.15 129.16,18.52 130.58,18.52 130.81,18.29 130.81,17.27 130.3,16.76 123.56,16.76 123.52,16.78 123.51,16.81 123.51,16.83 123.52,16.85 123.53,16.86 123.32,17.5 123.11,16.86 123.12,16.85 123.13,16.83 123.13,16.81 123.11,16.78 123.08,16.76 122.67,16.76 122.63,16.78 122.62,16.81 122.62,16.83 122.63,16.85 122.64,16.86 122.43,17.5 122.22,16.86 122.23,16.84 122.22,16.78 122.19,16.76 96.65,16.76 96.27,17.14 96.27,27.94 96.77,28.45 98.17,28.45
5V_SYS on BOTTOM (solid shape): 94.49,57.91 94.49,56.39 100.84,50.04 100.84,27.18 99.69,26.04 98.04,26.04 97.16,26.92 97.16,29.59 98.68,31.11 98.68,48.77 91.06,56.39 91.06,58.29 91.19,58.42 93.98,58.42
5V_SYS on BOTTOM (solid shape): outline of 688 points within 25.15,13.46 39.37,40.13
5V_SYS on INT1 (solid shape): outline of 2229 points within 24.51,5.71 98.55,23.62
5V_USB_HS on TOP (solid shape): 89.15,21.96 89.15,21.44 89.16,21.44 89.16,21.31 89.53,20.93 89.53,19.3 89.41,19.18 88.01,19.18 87.88,19.3 87.88,21.46 88.05,21.63 88.78,21.63 88.91,21.75 88.91,21.96 88.97,22.02 89.09,22.02
5V_USB_HS on BOTTOM (solid shape): outline of 104 points within 78.36,19.43 89.41,24
5V_USB_OTG on TOP (solid shape): 86.36,12.17 86.36,11.66 86.36,11.66 86.36,11.53 86.87,11.02 88.12,11.02 88.14,11 88.65,11 88.67,11.02 88.8,11.02 89.13,10.69 89.13,8.26 88.98,8.11 85.87,8.11 85.09,8.89 85.09,9.78 85.11,9.78 85.11,10.29 85.09,10.29 85.09,11.62 85.3,11.83 85.99,11.83 86.13,11.97 86.13,12.19 86.17,12.23 86.29,12.23
5V_USB_OTG on BOTTOM (solid shape): outline of 396 points within 20.83,5.21 87.38,20.57
GND on TOP (solid shape): 14.35,24.38 14.35,20.95 14.1,20.7 12.57,20.7 12.32,20.95 12.32,22.73 12.19,22.86 12.19,24.53 12.42,24.77 13.97,24.77
GND on TOP (solid shape): 45.14,42.04 49.02,42.04 49.15,41.91 49.15,40.01 49.02,39.88 44.58,39.88 44.45,40.01 44.45,42.04 44.51,42.1 45.07,42.1
GND on TOP (solid shape): 129.54,61.85 129.54,59.82 129.29,59.56 128.4,59.56 127,58.17 125.48,58.17 124.33,59.31 124.33,61.85 124.71,62.23 129.16,62.23
GND on TOP (solid shape): 130.18,65.02 130.18,63.25 130.05,63.12 128.14,63.12 128.02,63.25 128.02,64.9 128.27,65.15 130.05,65.15
GND on TOP (solid shape): 89.79,13.72 89.79,11.81 89.28,11.3 86.89,11.3 86.52,11.68 86.52,12.61 86.56,12.65 86.85,12.65 87.1,12.9 87.1,12.92 88.14,13.97 89.53,13.97
GND on TOP (solid shape): 100.58,72.14 100.58,71.25 100.33,70.99 98.04,70.99 97.66,71.37 96.8,71.37 96.65,71.53 96.65,72.39 96.9,72.64 100.08,72.64
GND on TOP (solid shape): 30.23,20.45 30.23,19.68 30.23,19.18 30.23,18.16 30.23,16.64 29.97,16.38 28.7,16.38 28.51,16.57 28.51,20.51 28.7,20.7 29.97,20.7
GND on TOP (solid shape): 92.56,66.69 92.56,66.42 92.58,66.4 92.58,66.02 92.58,66.02 92.58,64.92 92.56,64.9 92.56,64.62 92.33,64.39 91.15,64.39 90.97,64.57 90.97,66.71 91.19,66.93 92.33,66.93
GND on TOP (solid shape): 20.32,78.49 20.32,66.8 19.3,65.79 19.3,62.1 18.03,60.83 17.78,60.83 17.65,60.96 17.65,61.21 18.67,62.23 18.67,78.49 18.8,78.61 20.19,78.61
GND on TOP (solid shape): 51.56,14.99 51.56,13.84 51.56,13.59 51.82,13.34 51.82,11.51 52.17,11.15 53.52,11.15 53.59,11.07 53.59,10.49 53.54,10.44 50.34,10.44 50.16,10.62 50.16,15.24 50.29,15.37 51.18,15.37
GND on TOP (solid shape): 91.06,22.61 91.95,22.61 92.08,22.48 92.08,19.58 91.61,19.11 89.97,19.11 89.84,19.25 89.84,20.93 89.31,21.46 89.31,22.39 89.35,22.43 89.64,22.43 89.89,22.68 89.89,22.7 90.05,22.86 90.81,22.86
GND on TOP (solid shape): 127.38,20.7 127.38,20.55 127.38,20.35 127.38,20.34 127.38,19.86 127.37,19.83 127.33,19.81 127.25,19.81 127.25,18.8 127.13,18.67 125.6,18.67 125.35,18.92 125.35,20.7 125.6,20.95 127.13,20.95
GND on TOP (solid shape): 135.13,22.86 135.13,20.83 135,20.7 133.73,20.7 133.44,20.99 133.43,21.05 133.47,21.08 133.48,21.08 133.48,22.1 133.27,22.1 133.24,22.11 133.22,22.15 133.22,22.86 133.48,23.11 134.87,23.11
GND on TOP (solid shape): 36.32,16.89 36.32,16.54 36.3,16.51 35.07,16.51 35.05,16.51 34.86,16.32 34.86,15.43 34.8,15.37 34.29,15.37 34.04,15.62 32.64,15.62 32.51,15.75 32.51,16.2 32.53,16.24 32.56,16.26 33.92,16.26 33.92,16.27 34.16,16.51 34.16,16.76 34.32,16.92 36.3,16.92
GND on TOP (solid shape): 121.56,29.72 122,29.72 122.03,29.7 122.05,29.67 122.05,28.7 122.38,28.7 122.41,28.69 122.43,28.65 122.43,27.92 122.43,27.91 122.43,27.71 122.43,27.69 122.17,27.43 120.52,27.43 120.27,27.69 120.27,29.59 120.52,29.84 121.43,29.84
GND on TOP (solid shape): 37.72,42.04 37.72,41.67 37.72,37.97 37.34,37.59 35.18,37.59 34.92,37.34 34.92,36.94 34.57,36.58 33.53,36.58 33.4,36.7 33.4,38.23 33.53,38.35 34.54,38.35 35.07,38.35 36.55,38.35 36.83,38.35 36.83,38.63 36.83,40.38 36.83,40.39 36.83,40.64 36.32,41.15 36.32,42.04 36.45,42.16 37.59,42.16
GND on TOP (solid shape): 45.21,26.67 45.21,25.65 45.21,23.75 45.47,23.5 48.26,23.5 48.51,23.75 48.51,26.67 48.77,26.92 51.31,26.92 51.56,26.67 51.56,24.64 51.52,24.64 51.52,24.13 51.56,24.13 51.56,23.35 51.56,23.13 51.56,22.35 51.05,21.84 50.14,21.84 49.13,22.86 49,22.99 47.39,22.99 47.27,22.86 46.74,22.86 46.61,22.73 46.61,20.95 46.48,20.83 45.85,20.83 43.43,23.24 43.43,26.8 43.56,26.92 44.96,26.92
GND on TOP (solid shape): 83.06,5.05 83.06,4.34 83.02,4.26 82.93,4.24 82.31,4.08 82.13,3.46 82.11,3.42 82.08,3.4 82.04,3.4 81.89,3.55 81.89,5.16 82.04,5.31 82.8,5.31
GND on TOP (solid shape): 93.85,5.05 93.85,4.3 93.81,4.21 93.71,4.2 93.12,4.18 92.78,3.69 92.72,3.6 92.61,3.63 92.58,3.66 92.58,5.05 92.84,5.31 93.6,5.31
GND on TOP (solid shape): 149.44,99.49 149.48,99.48 149.49,99.44 149.49,79.04 149.48,79.01 149.44,78.99 146.81,78.99 146.56,79.25 146.56,81.28 146.18,81.66 146.18,84.58 147.57,85.98 147.57,91.31 146.18,92.71 141.48,92.71 137.92,96.27 126.36,96.27 126.11,96.52 126.11,98.3 125.86,98.55 16,98.55 1.4,83.95 1.4,78.74 3.17,76.96 3.17,31.37 7.11,27.43 7.11,22.73 6.22,21.84 6.22,15.37 8.26,13.34 8.26,6.1 8.89,5.46 12.07,5.46 15.75,1.78 30.51,1.78 31.08,1.21 31.42,1.21 31.45,1.17 72.42,1.17 73.03,1.78 74.68,1.78 75.18,1.27 75.18,0.56 75.17,0.52 75.13,0.51 0.56,0.51 0.52,0.52 0.51,0.56 0.51,99.44 0.52,99.48 0.56,99.49
GND on TOP (solid shape): outline of 128 points within 121.54,0.51 149.49,70.1
GND on TOP (solid shape): outline of 109 points within 5.46,35.43 26.42,78.61
GND on BOTTOM (solid shape): 110.49,47.12 110.49,43.94 110.24,43.69 106.93,43.69 106.68,43.94 106.68,47.12 106.93,47.37 110.24,47.37
GND on BOTTOM (solid shape): 91.21,5.37 93.65,5.37 93.73,5.29 93.73,4.88 92.15,3.31 90.53,3.31 90.41,3.42 90.41,4.43 90.43,4.44 90.43,5.09 90.25,5.27 90.25,5.62 90.32,5.7 90.88,5.7
GND on BOTTOM (solid shape): 83.06,5.54 83.06,4.76 82.51,4.21 82.5,4.2 82.3,4.07 82.17,3.87 82.17,3.86 81.61,3.31 79.86,3.31 79.5,3.66 79.5,6.01 79.63,6.14 82.46,6.14
GND on BOTTOM (solid shape): 71.5,56.9 71.5,56.26 71.25,56.01 71.22,56.01 71.02,56.01 71.01,56.01 69.96,56.01 69.95,56.01 69.75,56.01 69.74,56.01 68.69,56.01 68.68,56.01 68.48,56.01 68.47,56.01 67.82,56.01 67.56,56.26 67.56,56.9 67.82,57.15 71.25,57.15
GND on BOTTOM (solid shape): 94.11,76.07 94.11,75.06 93.85,74.8 93.83,74.8 93.62,74.8 93.62,74.8 92.82,74.8 92.81,74.8 92.61,74.8 92.6,74.8 92.2,74.8 92.08,74.68 91.97,74.68 91.95,74.7 91.55,74.7 91.31,74.93 91.31,76.07 91.57,76.33 93.85,76.33
GND on BOTTOM (solid shape): 50.83,47.83 50.83,45.09 50.69,44.95 50.39,44.95 50.09,45.25 49.85,45.25 49.84,45.26 46.56,45.26 46.55,45.28 46.42,45.28 46.35,45.34 43.81,45.34 43.69,45.47 43.69,45.72 44.96,46.99 45.82,46.99 45.83,47 46.19,47 47.24,48.06 50.6,48.06
GND on BOTTOM (solid shape): 49.66,41.4 49.66,38.23 49.4,37.97 43.94,37.97 43.69,38.23 43.69,39.62 43.94,39.88 45.85,39.88 46.1,40.13 46.35,40.13 46.35,40.11 46.86,40.11 46.86,40.13 47.5,40.13 47.5,40.11 48.01,40.11 48.01,40.13 48.51,40.13 48.64,40.26 48.64,41.4 48.77,41.53 49.53,41.53
GND on BOTTOM (solid shape): 58.81,56.16 59.08,56.16 59.25,55.99 59.25,55.78 59.4,55.62 59.4,55.01 59.33,54.94 58.9,54.94 58.62,54.66 58.62,54.48 58.47,54.33 58.24,54.33 58.09,54.18 58.09,53.85 58.03,53.78 57.59,53.78 57.53,53.85 57.53,54.61 57.66,54.74 58.04,54.74 58.19,54.89 58.19,54.94 58.21,54.98 58.24,54.99 58.26,54.99 58.26,55.5 58.24,55.5 58.21,55.51 58.19,55.55 58.19,55.63 58.1,55.71 57.69,55.71 57.67,55.72 57.66,55.73 57.6,55.78 57.6,55.99 57.81,56.2 58,56.2 58.1,56.3 58.67,56.3
GND on BOTTOM (solid shape): outline of 2144 points within 0.51,0.51 149.49,99.49
GND on GND (solid shape): outline of 35735 points within 0.51,0.51 149.49,99.49
GND on INT1 (solid shape): 148.46,26.67 149.44,26.67 149.48,26.65 149.49,26.62 149.49,0.56 149.48,0.52 149.44,0.51 121.92,0.51 121.92,1.27 122.94,2.29 139.19,2.29 148.84,11.94 148.84,24.89 148.08,25.65 148.08,27.43 148.46,27.43
GND on INT1 (solid shape): outline of 3635 points within 0.51,0.51 149.49,99.49
GND on INT1 (solid shape): outline of 4447 points within 12.7,23.75 65.72,66.67
P3V3_SDA on TOP (solid shape): 143.76,82.93 143.76,81.66 143.64,81.53 142.49,81.53 141.48,80.52 140.99,80.52 140.59,80.52 140.46,80.39 140.46,77.98 140.34,77.85 138.68,77.85 138.56,77.98 138.56,81.66 138.68,81.79 140.08,81.79 140.72,82.42 141.48,82.42 141.61,82.55 142.11,83.06 143.64,83.06
P3V3_SDA on TOP: 122.68,69.09 126.24,69.09 126.36,68.96 126.36,68.07 126.24,67.94 124.97,67.94 124.84,67.82 124.84,66.8 124.71,66.67 122.68,66.67 122.56,66.8 122.56,68.96
P3V3_SDA on BOTTOM: 140.08,80.9 140.21,80.77 140.21,78.11 139.95,77.85 130.18,77.85 129.67,77.34 129.67,76.83 128.4,75.56 128.4,74.3 128.65,74.04 128.65,73.28 128.52,73.15 127.89,73.15 127.64,72.9 127.64,72.14 128.14,71.63 129.29,71.63 129.41,71.5 129.41,70.1 129.29,69.98 128.27,69.98 128.02,70.23 127.38,70.23 127.13,69.98 127.13,68.96 126.62,68.45 123.57,68.45 121.92,70.1 121.92,76.45 123.95,78.49 123.95,79.88 124.97,80.9
P5V_SDA on TOP (solid shape): 139.83,67.06 139.83,62.87 138.43,61.47 130.94,61.47 130.56,61.85 130.56,62.78 130.74,62.96 130.74,65.32 131,65.58 131,66.23 131.05,66.29 131.19,66.29 131.24,66.23 131.24,65.93 131.29,65.89 131.56,65.89 131.64,65.81 131.64,65.44 131.97,65.12 132.12,65.12 132.13,65.13 132.28,65.13 132.9,64.5 132.9,63.57 133.1,63.37 137.03,63.37 137.41,63.75 137.41,67.18 137.54,67.31 139.57,67.31
P5V_SDA on TOP (solid shape): 146.18,80.9 146.18,79.38 145.67,78.87 145.67,77.22 143.64,75.18 139.57,75.18 139.45,75.31 139.45,75.95 139.57,76.07 142.62,76.07 142.75,76.2 142.75,76.45 142.88,76.45 142.88,77.47 142.75,77.47 142.75,78.61 142.49,78.87 142.49,79.22 143.83,79.22 143.83,78.9 143.81,78.87 143.8,78.82 143.79,78.76 143.79,78.71 143.8,78.66 143.81,78.61 143.84,78.56 143.87,78.52 143.9,78.48 143.94,78.44 143.99,78.42 144.04,78.4 144.09,78.39 144.15,78.38 144.2,78.39 144.25,78.4 144.3,78.42 144.35,78.44 144.39,78.48 144.42,78.52 144.45,78.56 144.48,78.61 144.49,78.66 144.5,78.71 144.5,78.76 144.49,78.82 144.48,78.87 144.46,78.9 144.46,79.22 144.65,79.22 144.65,80.49 143.64,80.49 143.64,79.22 142.49,79.22 142.49,80.9 142.62,81.03 146.05,81.03
P5V_SDA on BOTTOM: 137.29,66.93 137.54,66.67 139.7,66.67 139.95,66.93 139.95,68.83 142.88,71.75 142.88,76.2 142.75,76.33 139.45,76.33 139.19,76.07 139.19,71.75 137.29,69.85
P5V_SDA_S on TOP (solid shape): 137.02,66.18 137.01,66.17 137.01,65.66 137.03,65.66 137.03,64.01 136.91,63.88 135.25,63.88 135.13,64.01 135.13,64.52 134.11,65.53 134.11,65.66 134.13,65.66 134.13,66.19 134.24,66.29 136.91,66.29
P5V_SDA_S on INT1 (solid shape): outline of 2928 points within 18.16,2.03 148.59,67.94
VDD_SOC_IN on BOTTOM (solid shape): 60.2,55.45 60.2,54.94 60.07,54.81 60.07,54.66 60.06,54.6 60.07,54.53 60.07,54.38 60.02,54.33 59.49,54.33 59.46,54.31 59.45,54.3 59.33,54.18 59.29,54.18 59.29,54.13 59.28,54.13 59.28,53.75 59.21,53.67 58.85,53.67 58.8,53.72 58.8,54.62 58.97,54.79 59.4,54.79 59.46,54.79 59.54,54.86 59.54,54.87 59.66,54.99 59.71,54.99 59.71,55.04 59.72,55.04 59.72,55.47 59.74,55.5 60.15,55.5
VDD_SOC_IN on BOTTOM (solid shape): 46.74,44.94 47.24,44.94 47.24,44.96 47.7,44.96 47.7,44.94 48.21,44.94 48.21,44.96 48.72,44.96 48.72,44.94 49.23,44.94 49.23,44.96 49.91,44.96 50.29,44.58 50.29,43.56 48.39,41.66 48.39,40.64 48.13,40.39 48.01,40.39 48.01,40.41 47.5,40.41 47.5,40.39 46.86,40.39 46.86,40.41 46.35,40.41 46.35,40.39 41.53,40.39 41.02,40.89 41.02,42.16 41.27,42.42 45.59,42.42 45.97,42.8 45.97,43.94 45.97,44.7 46.23,44.96 46.74,44.96
VDD_SOC_IN on BOTTOM (solid shape): 58.98,56.82 59.23,56.82 59.31,56.74 59.31,56.4 59.29,56.36 59.26,56.35 59,56.35 58.69,56.67 58.17,56.67 57.91,56.41 57.81,56.41 57.45,56.05 57.45,55.72 57.61,55.56 57.89,55.56 57.96,55.49 57.96,54.94 57.91,54.89 57.77,54.9 57.69,54.89 57.59,54.89 57.57,54.86 57.26,54.86 57.21,54.89 57.16,54.9 57.09,54.9 56.99,54.88 56.97,54.9 56.77,55.09 56.78,55.25 56.77,55.31 56.77,55.45 56.59,55.63 56.26,55.63 56.21,55.68 56.21,56.03 56.26,56.08 56.79,56.08 56.97,56.26 57.01,56.26 57.02,56.26 57.28,56.29 57.42,56.52 57.43,56.54 57.43,56.72 57.6,56.89 57.74,56.89 57.95,56.95 58.07,57.13 58.09,57.15 58.65,57.15
VDD_SOC_IN on INT1 (solid shape): outline of 455 points within 48.13,43.31 60.07,56.64
BL- on TOP (solid shape): 96.95,70.87 97.51,70.87 97.9,70.47 100.47,70.47 100.58,70.36 100.58,69.85 99.44,68.71 99.44,67.44 99.31,67.31 97.41,67.31 97.28,67.44 97.28,67.94 97.92,68.58 97.92,69.22 97.79,69.34 96.01,69.34 95.89,69.47 95.89,71.09 96.11,71.32 96.49,71.32
BL- on BOTTOM (solid shape): 96.52,71.22 96.52,69.95 96.44,69.88 94.56,69.88 94.51,69.93 94.51,71.4 94.56,71.45 96.29,71.45
DC_5V_IN on TOP (solid shape): 15.24,15.04 15.24,11.67 15.24,11.66 15.24,11.46 15.24,11.45 15.24,6.86 14.86,6.48 10.16,6.48 9.53,7.11 9.53,15.01 9.65,15.14 9.88,15.14 9.91,15.11 9.91,15.09 10.41,15.09 10.41,15.11 10.44,15.14 11.15,15.14 11.18,15.11 11.18,15.09 11.68,15.09 11.68,15.11 11.71,15.14 11.94,15.14 12.24,15.44 14.83,15.44
DCDC_3V3 on TOP (solid shape): 122.56,30.86 122.56,30.75 122.54,30.73 122.54,30.21 122.3,29.97 121.67,29.97 121.41,30.23 121.41,30.86 121.67,31.11 122.3,31.11
DCDC_3V3 on TOP (solid shape): 48.01,28.57 48.01,28.32 47.88,28.19 47.24,28.19 47.24,28.2 46.74,28.2 46.74,28.19 46.1,28.19 45.97,28.32 45.97,28.57 46.1,28.7 47.88,28.7
DCDC_3V3 on TOP (solid shape): 52.32,18.24 52.83,18.24 52.83,18.29 54.1,18.29 54.23,18.16 54.23,16 53.98,15.75 51.31,15.75 51.05,16 51.05,18.16 51.18,18.29 52.32,18.29
DCDC_3V3 on TOP (solid shape): 87,75.06 87,73.28 86.99,73.28 86.99,72.39 86.87,72.26 85.6,72.26 84.84,73.03 83.44,73.03 83.31,73.15 83.31,75.06 83.44,75.18 86.87,75.18
DCDC_3V3 on TOP (solid shape): 34.67,42.77 34.67,42.29 34.92,42.04 34.92,41.78 34.8,41.66 33.02,41.66 32.89,41.78 32.89,42.01 33.79,42.9 34.54,42.9
DCDC_3V3 on TOP (solid shape): 58.04,65.79 58.04,65.63 58.04,65.43 58.04,65.42 58.04,64.5 58.04,64.49 58.04,64.29 58.04,64.28 58.04,63.63 57.78,63.37 56.64,63.37 56.57,63.45 56.57,65.96 56.64,66.04 57.78,66.04
DCDC_3V3 on BOTTOM (solid shape): 72.14,55.63 72.14,54.74 72.01,54.61 68.07,54.61 67.82,54.86 67.82,55.5 68.07,55.75 71.35,55.75 72.01,55.75
DCDC_3V3 on BOTTOM (solid shape): outline of 148 points within 27.18,59.56 32.51,68.71
DCDC_3V3 on INT1 (solid shape): outline of 39323 points within 3.17,7.56 143,98.42
DCDC_OUT on TOP (solid shape): 46.74,49.02 46.74,45.73 47.89,44.58 48.51,44.58 48.77,44.32 48.77,42.93 48.51,42.67 45.72,42.67 45.47,42.42 45.01,42.42 45.01,42.44 44.5,42.44 44.5,42.42 44.2,42.42 44.07,42.55 41.15,42.55 41.02,42.67 41.02,44.96 41.27,45.21 44.32,45.21 44.84,45.73 44.84,48.91 45.09,49.15 46.61,49.15
DCDC_OUT on BOTTOM (solid shape): 45.47,44.96 45.47,43.94 45.47,42.93 45.47,42.8 45.34,42.67 41.02,42.67 40.89,42.8 40.89,44.96 41.02,45.09 45.34,45.09
ENET_3V3 on TOP (solid shape): 110.11,40.93 110.11,39.4 109.86,39.15 108.68,39.15 108.47,39.36 108.41,39.44 108.35,39.5 108.34,39.52 108.33,39.54 108.33,40.93 108.58,41.18 109.86,41.18
ENET_3V3 on TOP (solid shape): 103.25,48.55 103.25,47.8 103.24,47.76 103.24,47.56 103.25,47.52 103.25,47.4 103.12,47.28 102.23,47.28 101.98,47.53 101.98,48.55 102.11,48.67 103.12,48.67
ENET_3V3 on BOTTOM (solid shape): outline of 234 points within 101.73,29.46 116.84,53.34
FLASH_VCC on TOP (solid shape): 56.77,24.77 56.77,19.56 55.75,18.54 49.66,18.54 49.42,18.78 49.42,19.18 49.4,19.2 49.4,19.56 51.82,21.97 51.82,24.89 51.94,25.02 56.52,25.02
LCD_3V3 on BOTTOM (solid shape): 90.42,74.4 90.93,74.4 90.95,74.42 91.42,74.42 91.44,74.4 91.95,74.4 91.97,74.42 94.11,74.42 94.23,74.3 94.23,72.59 93.27,71.63 93.27,69.95 93.24,69.93 93.07,69.93 93.04,69.95 93.04,71.68 92.58,72.14 92.58,72.77 91.82,73.53 89.66,73.53 89.53,73.66 89.53,74.3 89.66,74.42 90.4,74.42
LDO_1V8 on TOP (solid shape): 49.15,22.48 49.15,19.2 49.13,19.18 49.13,18.67 49.15,18.65 49.15,18.33 49.53,17.95 49.53,15.73 49.53,10.31 49.53,8.89 49.4,8.76 48.51,8.76 48.26,9.02 48.26,16 47.24,17.02 47.24,22.48 47.5,22.73 48.9,22.73
MCU_DCDC_IN on TOP (solid shape): 43.69,47.12 43.69,45.85 43.43,45.59 41.27,45.59 40.26,44.58 39.37,44.58 39.12,44.32 39.12,42.8 38.73,42.42 37.59,42.42 37.47,42.55 37.47,43.69 36.58,44.58 36.58,46.99 36.7,47.12 40.51,47.12 40.6,47.2 43.61,47.2
MCU_DCDC_IN on BOTTOM (solid shape): 53.52,52.86 53.61,52.86 53.64,52.83 53.64,52.81 54.15,52.81 54.15,52.83 54.18,52.86 54.64,52.86 54.67,52.83 54.67,52.51 54.61,52.45 54.25,52.45 54.18,52.37 54.18,52.22 54.15,52.2 52.96,52.2 52.67,51.91 52.67,51.4 52.57,51.31 52.32,51.31 51.94,50.93 51.92,50.93 51.92,50.43 51.89,50.39 51.49,50.39 51.44,50.44 51.44,50.93 51.94,51.44 51.94,51.83 52.39,52.27 52.39,52.39 52.98,52.98 53.39,52.98
MCU_DCDC_IN on INT1 (solid shape): 54.12,53.44 54.19,53.41 54.22,53.33 54.41,53.01 54.76,53.11 54.85,53.15 54.93,53.11 54.95,53.08 54.99,53.05 55.03,52.97 54.99,52.89 54.94,52.85 54.91,52.8 54.84,52.73 54.84,52.68 53.69,51.53 53.57,51.46 53.5,51.34 51.44,49.28 50.42,49.28 47.28,46.13 46.83,46.13 46.8,46.1 43.31,46.1 43.18,46.23 43.18,47.07 43.33,47.22 46.46,47.22 46.48,47.24 46.76,47.24 50.04,50.52 50.99,50.52 52.6,52.13 52.6,52.48 53.57,53.44
MCU_DCDC_IN_3V3 on TOP (solid shape): 35.94,46.86 35.94,44.83 36.96,43.81 36.96,42.67 36.7,42.42 36.32,42.42 35.56,43.18 35.56,43.2 34.92,43.2 34.92,43.18 34.29,43.18 34.29,43.2 33.78,43.2 33.77,43.19 33.66,43.31 33.66,43.81 32.89,44.58 32.89,46.86 33.15,47.12 35.69,47.12
NVCC_SD on TOP (solid shape): 40.77,41.91 40.77,39.22 40.74,39.19 40.74,38.68 40.77,38.66 40.77,37.72 40.64,37.59 40.26,37.59 40.13,37.72 40.13,38.35 40.01,38.48 38.23,38.48 38.1,38.61 38.1,42.04 38.23,42.16 38.86,42.16 39.24,42.55 40.13,42.55
NVCC_SD on BOTTOM (solid shape): 49.89,50.69 49.89,50.54 49.91,50.52 49.91,50.06 49.89,50.04 49.89,49.64 49.66,49.4 48.77,49.4 48.39,49.78 48.39,50.29 49.02,50.93 49.66,50.93
PERI_3V3 on TOP (solid shape): 90.93,75.95 90.93,74.8 90.55,74.42 89.53,74.42 89.28,74.17 89.28,72.64 88.9,72.26 87.88,72.26 87.63,72.52 87.63,76.07 87.76,76.2 90.68,76.2
PERI_3V3 on BOTTOM (solid shape): 90.93,75.69 90.93,74.93 90.7,74.7 90.42,74.7 90.4,74.68 89.92,74.68 89.66,74.93 89.66,75.69 89.92,75.95 90.68,75.95
SDA_USBSHIELD on TOP (solid shape): 149.48,78.49 149.48,67.31 149.22,67.06 145.41,67.06 145.29,67.18 145.29,68.58 145.41,68.71 146.69,68.71 147.32,69.34 147.32,78.49 147.45,78.61 149.35,78.61
SDRAM_3V3 on BOTTOM (solid shape): outline of 88 points within 29.51,53.9 37.52,60.4
SENSOR_3V3 on TOP (solid shape): 61.85,82.42 61.85,81.68 61.84,81.63 61.84,81.43 61.85,81.39 61.85,81.15 61.72,81.03 61.21,81.03 61.09,81.15 61.09,81.79 60.83,82.04 58.8,82.04 56.64,79.88 56.64,79.12 56.39,78.87 55.75,78.87 55.63,78.99 55.63,79.15 55.63,79.35 55.63,79.36 55.63,80.26 55.24,80.64 54.36,80.64 53.85,80.14 53.85,74.93 54.86,73.91 55.63,73.91 55.75,74.04 55.75,75.82 55.88,75.95 56.52,75.95 56.9,75.56 56.9,74.42 57.4,73.91 58.55,73.91 59.05,73.41 59.05,71.63 58.93,71.5 58.69,71.5 58.65,71.51 58.45,71.51 58.4,71.5 58.29,71.5 58.17,71.63 58.17,72.64 57.66,73.15 54.1,73.15 52.96,74.3 52.96,80.39 54.36,81.79 56.24,81.79 56.26,81.77 56.77,81.77 56.79,81.79 57.28,81.79 57.51,82.02 57.55,82.06 58.04,82.55 61.72,82.55
VLDO_3V3 on TOP (solid shape): 57.11,15.41 57.11,14.31 57.13,14.29 57.13,13.84 57.15,13.82 57.15,13.49 57.12,13.46 57.12,12.95 57.15,12.93 57.15,11.81 57.4,11.56 57.4,10.99 57.36,10.94 55.35,10.94 55.12,11.18 55.12,15.37 55.24,15.49 57.02,15.49
N99781670 on TOP (solid shape): 54.22,52.58 54.43,52.35 54.73,52.42 54.73,52.43 54.77,52.44 54.94,52.44 54.97,52.42 54.97,52.25 54.89,52.17 53.98,52.17 53.96,52.15 53.93,52.15 53.16,51.38 53.16,51.38 52.53,50.75 52.53,50.37 51.29,49.13 51.24,49.15 50.84,49.13 50.71,48.74 50.7,48.66 50.71,48.55 49.91,47.75 49.91,45.34 49.66,45.09 48.13,45.09 48.01,45.21 48.01,49.4 48.23,49.63 48.26,49.63 48.48,49.85 48.51,49.83 48.89,49.91 48.97,50.3 48.96,50.33 49.54,50.91 50.53,50.91 50.63,51.01 50.66,51.01 51.2,51.16 51.36,51.7 51.35,51.73 51.84,52.22 51.85,52.22 51.93,52.27 52,52.34 52.01,52.35 52.05,52.37 52.63,52.37 52.73,52.32 52.84,52.3 53.01,52.28 53.17,52.36 53.19,52.37 53.21,52.37 53.29,52.37 53.44,52.53 53.55,52.54 53.64,52.58
N99781747 on TOP (solid shape): 37.59,15.88 37.59,14.61 37.85,14.35 43.31,14.35 43.43,14.22 43.43,12.32 43.31,12.19 40.89,12.19 40.51,11.81 39.5,11.81 39.24,11.56 38.72,11.56 38.71,11.56 38.51,11.56 38.5,11.56 38.23,11.56 38.1,11.43 38.1,10.92 37.85,10.67 34.8,10.67 34.67,10.79 34.67,14.61 35.13,15.06 35.13,16.21 35.18,16.26 37.21,16.26
N99781762 on TOP (solid shape): 32.03,21.82 32.03,17.93 32.41,17.55 33.68,17.55 33.71,17.53 33.71,17.2 33.68,17.17 31.54,17.17 31.5,17.17 31.27,16.94 30.75,16.94 30.61,17.08 30.61,17.17 30.61,17.37 30.61,17.38 30.61,17.75 30.76,17.91 30.76,20.68 30.73,20.7 30.61,20.83 30.61,21.19 30.63,21.21 30.63,21.72 30.61,21.74 30.61,21.84 30.73,21.97 31.88,21.97
N99781791 on TOP (solid shape): 33.67,16.9 33.67,16.56 33.65,16.52 33.62,16.51 32.38,16.51 32.26,16.38 32.26,15.37 32.38,15.24 32.77,15.24 33.02,14.99 33.02,11.05 32.64,10.67 31.5,10.67 31.37,10.79 31.37,16.64 31.65,16.92 33.66,16.92
N99816488 on TOP (solid shape): 119.89,9.18 119.89,3.21 119.63,2.95 117.22,2.95 116.97,3.21 116.97,4.32 117.45,5.58 116.97,6.84 116.97,9.18 117.22,9.43 119.63,9.43
